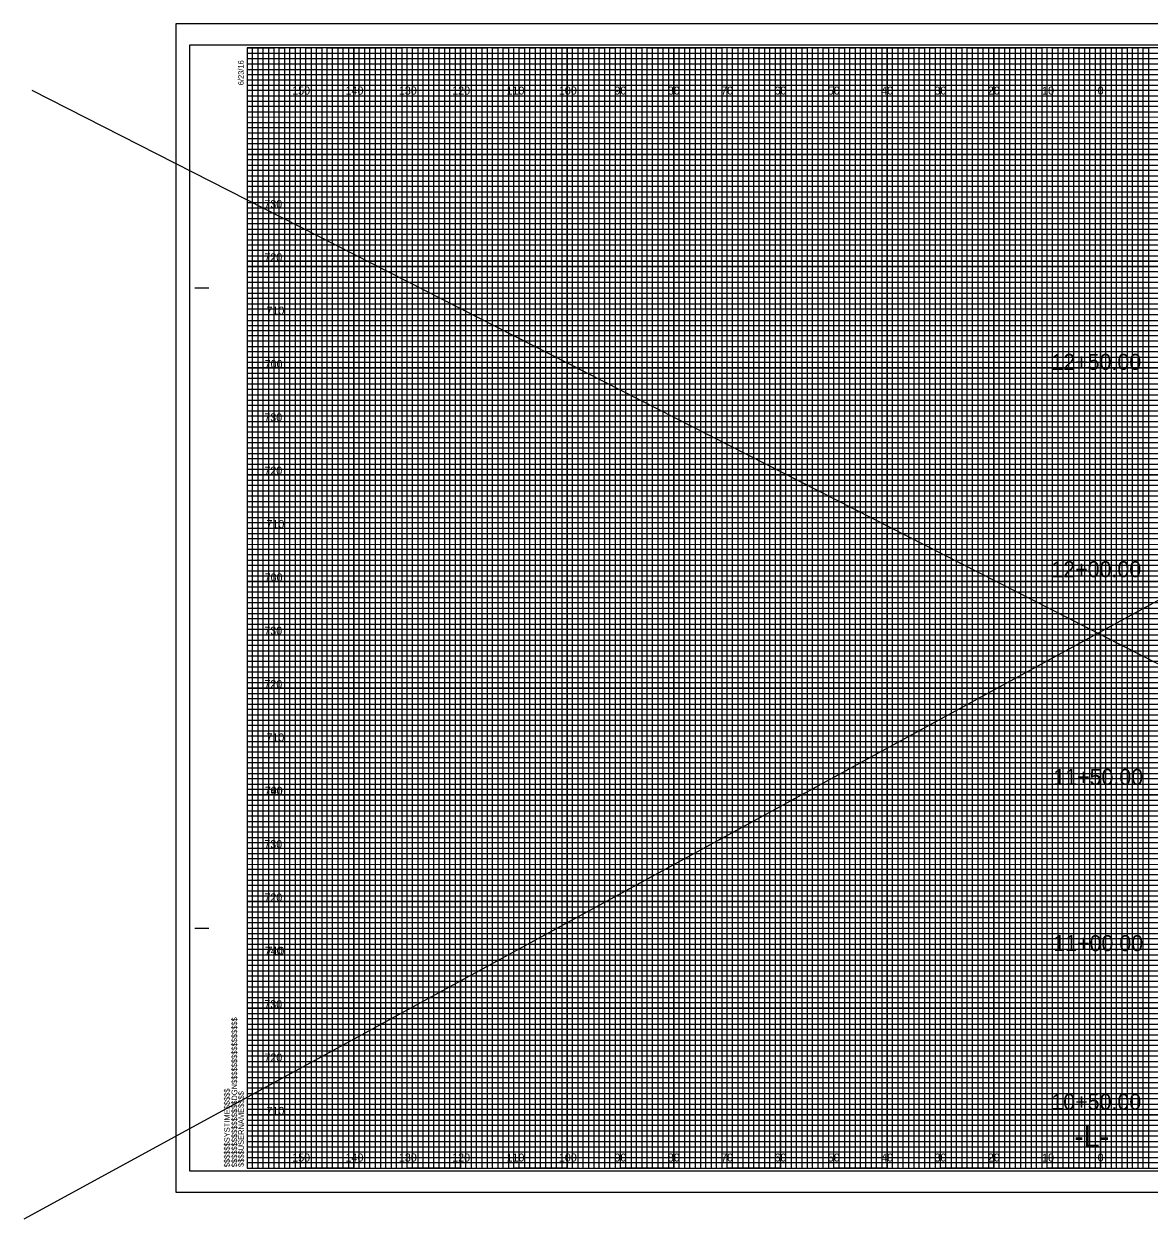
# Model space of a CAD drawing. Extents: x -98 to 717, y -10 to 1974.
# Drawn here: x -41.9 to 169.1, y -9.5 to 214.5 of the extents above; entities that cross this region are included whole.
import ezdxf

# ---------------------------------------------------------------- set-up
doc = ezdxf.new("R2010")
doc.units = 0
for name, color, linetype in [('Default', 7, 'Continuous'), ('Exist XS Center Line Elevation Label', 7, 'Continuous'), ('Prop CMT Conc Surface', 7, 'Continuous'), ('Prop CMT Concrete Structures', 7, 'Continuous'), ('Prop CMT Pvmt Course 1', 7, 'Continuous'), ('Prop CMT Pvmt Course 1 CG', 7, 'Continuous'), ('Prop CMT Pvmt Course 2', 7, 'Continuous'), ('Prop CMT Pvmt Course 3', 7, 'Continuous'), ('Prop CMT Pvmt Surface', 7, 'Continuous'), ('Prop CMT Shld Paved Course 3', 7, 'Continuous'), ('Prop CMT Subgrade Earthwork', 7, 'Continuous'), ('Prop XS Earthwork Shape', 7, 'Continuous'), ('Prop XS Elevation Labels', 7, 'Continuous'), ('Typical Curb CELL', 7, 'Continuous')]:
    doc.layers.add(name, color=color, linetype=linetype)

msp = doc.modelspace()

# ---------------------------------------------------------------- linework, layer by layer
at = {"layer": 'Default'}
for p, q in [((351.51, 205.03), (-41.86, -9.54)), ((-40.39, 202.07), (375.17, -9.54))]:
    msp.add_line(p, q, dxfattribs=at)
at = {"layer": 'Exist XS Center Line Elevation Label'}
for p, q in [((0, 209), (260, 209)), ((260, 207.98), (0, 207.98)), ((0, 207.98), (0, 207)), ((0, 207), (260, 207)), ((260, 205.89), (0, 205.89)), ((0, 205.89), (0, 204)), ((0, 204), (320, 204))]:
    msp.add_line(p, q, dxfattribs=at)
for points in [[(0, 203), (270, 203), (320, 203), (320, 202), (0, 202)], [(0, 201), (320, 201), (320, 199), (0, 199)], [(0, 198), (320, 198), (320, 197), (0, 196.98)], [(0, 196), (320, 196), (320, 194), (0, 194)], [(0, 193), (320, 193), (320, 192), (0, 192)], [(0, 191), (320, 191), (320, 189), (0, 189)], [(0, 188), (320, 188), (320, 187), (0, 187)], [(0, 186), (320, 186), (320, 184), (0, 184)], [(0, 183), (320, 183), (320, 182), (0, 182)], [(0, 181), (320, 181), (320, 179), (0, 179)], [(0, 178), (320, 178), (320, 177), (0, 177)], [(0, 176), (320, 176), (320, 173.95), (320, 173), (320, 172), (0, 172)], [(0, 174), (320, 174), (320, 173), (0, 173)], [(0, 171), (320, 171), (320, 169), (0, 169.03)], [(0, 169.03), (320, 169), (320, 168), (0, 168)], [(0, 167), (320, 167), (320, 166), (0, 166)], [(0, 164), (320, 164), (320, 163), (0, 163)], [(0, 162), (320, 162), (320, 161), (0, 161)], [(-0.07, 158.89), (320, 158.89), (320, 157.88), (-0.07, 157.88)], [(0, 157), (320, 157), (320, 156), (0, 156)], [(0, 154), (320, 154), (320, 153), (0, 153)], [(0, 152), (320, 152), (320, 151), (0, 151)], [(0, 149), (320, 149), (320, 148), (0, 148)], [(0, 147), (320, 147), (320, 146), (0, 146)], [(0, 144), (320, 144), (320, 143), (0, 143)], [(0, 142), (320, 142), (320, 141), (0, 141)], [(0, 139), (320, 139), (319.99, 137.98), (0, 138)], [(0, 137), (320, 137), (320, 136), (0, 136)], [(0, 134), (320, 134), (320, 133), (0, 133)], [(0, 132), (320, 132), (320, 131), (0, 131)], [(0, 129), (320, 129), (320, 128), (0, 128)], [(0, 127), (320, 127), (320, 126), (0, 126)], [(0, 124), (320, 124), (320, 123), (0, 123)], [(0, 122), (320, 122), (320, 121), (0, 121)], [(0, 119), (320, 119), (320, 118), (0, 118)], [(0, 116.99), (320.07, 116.91), (320, 116), (0, 116)], [(0, 114), (320, 114), (320, 113), (0, 113)], [(0, 112), (320, 112), (320, 111), (0, 111)], [(0, 109), (320, 109), (320, 108), (0, 108)], [(0, 107), (320, 107), (320, 106), (0, 106)], [(0, 104), (320, 104), (320, 103), (0, 103)], [(0, 102), (320, 102), (320, 101), (0, 101)], [(0, 99), (320, 99), (320, 98), (0, 98)], [(0, 97), (320, 97), (320, 96), (0, 96)], [(0, 94), (320, 94), (320, 93), (0, 93)], [(0, 92), (320, 92), (320, 91), (0, 91)], [(0, 89), (320, 89), (320, 88), (0, 88)], [(0, 87), (320, 87), (320, 86), (0, 86)], [(0, 84), (320, 84), (320, 83), (0, 83)], [(0, 82), (320, 82), (320, 81), (0, 81)], [(0, 79), (320, 79), (319.99, 77.98), (0, 78)], [(0, 77), (320, 77), (320, 76), (0, 76)], [(0, 74), (320, 74), (320, 73), (0, 73)], [(0, 72), (320, 72), (320, 71), (0, 71)], [(0, 69), (320, 69), (320, 68), (0, 68)], [(0, 67), (320, 67), (320, 66), (0, 66)], [(0, 64), (320, 64), (320, 63), (0, 63)], [(0, 62), (320, 62), (320, 61), (0, 61)], [(0, 59), (320, 59), (320, 58), (0, 58)], [(0, 56.99), (320.07, 56.91), (320, 56), (0, 56)], [(0, 54), (320, 54), (320, 53), (0, 53)], [(0, 52), (320, 52), (320, 51), (0, 51)], [(0, 49), (320, 49), (320, 48), (0, 48)], [(0, 47), (320, 47), (320, 46), (0, 46)], [(0, 44), (320, 44), (320, 43), (0, 43)], [(0, 42), (320, 42), (320, 41), (0, 41)], [(0, 39), (320, 39), (320, 38), (0, 38)], [(0, 37), (320, 37), (320, 36), (0, 36)], [(0, 34), (320, 34), (320, 33), (0, 33)], [(0, 32), (320, 32), (320, 31), (0, 31)], [(0, 29), (320, 29), (320, 28), (0, 28)], [(0, 27), (320, 27), (320, 26), (0, 26)], [(0, 24), (320, 24), (320, 23), (0, 23)], [(0, 22), (320, 22), (320, 21), (0, 21)], [(0, 19), (320, 19), (320, 18), (0, 18)], [(0, 17), (320, 17), (320, 16), (0, 16)], [(0, 14), (320, 14), (320, 13), (0, 13)], [(0, 12), (320, 12), (320, 11), (0, 11)], [(0, 9), (320, 9), (320, 8), (0, 8)], [(0, 7), (320, 7), (320, 6), (0, 6)], [(0, 4), (320, 4), (320, 3), (0, 3)], [(0, 2), (320, 2), (320, 1), (0, 1)]]:
    msp.add_lwpolyline(points, dxfattribs=at)
at = {"layer": 'Prop CMT Conc Surface'}
for p, q in [((-9.8, 165), (-7.3, 165)), ((-9.7, 165), (-7.2, 165)), ((-9.8, 45), (-7.3, 45)), ((-9.7, 45), (-7.2, 45)), ((0, 0), (0, 0)), ((0, 0), (0, 0)), ((0, 0), (0, 0)), ((0, 0), (0, 0)), ((0, 0), (0, 0)), ((0, 0), (0, 0)), ((0, 0), (0, 0))]:
    msp.add_line(p, q, dxfattribs=at)
msp.add_lwpolyline([(320, 210), (0, 210), (0, 0), (320, 0)], close=True, dxfattribs=at)
at = {"layer": 'Prop CMT Concrete Structures'}
for p, q in [((10, 0), (10, 210)), ((20, 0), (20, 210)), ((30, 0), (30, 210)), ((40, 0), (40, 210)), ((50, 0), (50, 210)), ((60, 0), (60, 210)), ((70, 0), (70, 210)), ((80, 0), (80, 210)), ((90, 0), (90, 210)), ((100, 0), (100, 210)), ((110, 0), (110, 210)), ((120, 0), (120, 210)), ((130, 0), (130, 210)), ((140, 0), (140, 210)), ((150, 0), (150, 210)), ((160, 0), (160, 210)), ((0, 200), (320, 200)), ((0, 190), (320, 190)), ((0, 180), (320, 180)), ((0, 170), (320, 170)), ((0, 160), (320, 160)), ((0, 150), (320, 150)), ((0, 140), (320, 140)), ((0, 130), (320, 130)), ((0, 120), (320, 120)), ((0, 110), (320, 110)), ((0, 100), (320, 100)), ((0, 90), (320, 90)), ((0, 80), (320, 80)), ((0, 70), (320, 70)), ((0, 60), (320, 60)), ((0, 50), (320, 50)), ((0, 40), (320, 40)), ((0, 30), (320, 30)), ((0, 20), (320, 20)), ((0, 10), (320, 10))]:
    msp.add_line(p, q, dxfattribs=at)
at = {"layer": 'Prop CMT Pvmt Course 2'}
msp.add_lwpolyline([(-13.4, -4.5), (323.3, -4.5), (323.3, 214.5), (-13.4, 214.5)], close=True, dxfattribs=at)
at = {"layer": 'Prop CMT Pvmt Course 3'}
msp.add_lwpolyline([(-10.8, -0.5), (322.4, -0.5), (322.4, 210.5), (-10.8, 210.5)], close=True, dxfattribs=at)
at = {"layer": 'Prop CMT Pvmt Surface'}
for p, q in [((323.3, 214.5), (-13.4, 214.5)), ((-13.4, 214.5), (-13.4, -4.5)), ((-13.4, -4.5), (323.3, -4.5))]:
    msp.add_line(p, q, dxfattribs=at)
at = {"layer": 'Prop CMT Subgrade Earthwork'}
for points in [[(0, 0), (1, 0), (1, 210), (2, 210), (2, 0)], [(2, 0), (3, 0), (3, 210), (4, 210), (4, 0)], [(5, 0), (6, 0), (6, 210), (7, 210), (7, 0)], [(7, 0), (8, 0), (8, 210), (9, 210), (9, 0)], [(10, 0), (11, 0), (11, 210), (12, 210), (12, 0)], [(12, 0), (13, 0), (13, 210), (14, 210), (14, 0)], [(15, 0), (16, 0), (16, 210), (17, 210), (17, 0)], [(17, 0), (18, 0), (18, 210), (19, 210), (19, 0)], [(20, 0), (21, 0), (21, 210), (22, 210), (22, 0)], [(22, 0), (23, 0), (23, 210), (24, 210), (24, 0)], [(25, 0), (26, 0), (26, 210), (27, 210), (27, 0)], [(27, 0), (28, 0), (28, 210), (29, 210), (29, 0)], [(30, 0), (31, 0), (31, 210), (32, 210), (32, 0)], [(32, 0), (33, 0), (33, 210), (34, 210), (34, 0)], [(35, 0), (36, 0), (36, 210), (37, 210), (37, 0)], [(37, 0), (38, 0), (38, 210), (39, 210), (39, 0)], [(40, 0), (41, 0), (41, 210), (42, 210), (42, 0)], [(42, 0), (43, 0), (43, 210), (44, 210), (44, 0)], [(45, 0), (46, 0), (46, 210), (47, 210), (47, 0)], [(47, 0), (48, 0), (48, 210), (49, 210), (49, 0)], [(50, 0), (51, 0), (51, 210), (52, 210), (52, 0)], [(52, 0), (53, 0), (53, 210), (54, 210), (54, 0)], [(55, 0), (56, 0), (56, 210), (57, 210), (57, 0)], [(57, 0), (58, 0), (58, 210), (59, 210), (59, 0)], [(60, 0), (61, 0), (61, 210), (62, 210), (62, 0)], [(62, 0), (63, 0), (63, 210), (64, 210), (64, 0)], [(65, 0), (66, 0), (66, 210), (67, 210), (67, 0)], [(67, 0), (68, 0), (68, 210), (69, 210), (69, 0)], [(70, 0), (71, 0), (71, 210), (72, 210), (72, 0)], [(72, 0), (73, 0), (73, 210), (74, 210), (74, 0)], [(75, 0), (76, 0), (76, 210), (77, 210), (77, 0)], [(77, 0), (78, 0), (78, 210), (79, 210), (79, 0)], [(80, 0), (81, 0), (81, 210), (82, 210), (82, 0)], [(82, 0), (83, 0), (83, 210), (84, 210), (84, 0)], [(85, 0), (86, 0), (86, 210), (87, 210), (87, 0)], [(87, 0), (88, 0), (88, 210), (89, 210), (89, 0)], [(90, 0), (91, 0), (91, 210), (92, 210), (92, 0)], [(92, 0), (93, 0), (93, 210), (94, 210), (94, 0)], [(95, 0), (96, 0), (96, 210), (97, 210), (97, 0)], [(97, 0), (98, 0), (98, 210), (99, 210), (99, 0)], [(100, 0), (101, 0), (101, 210), (102, 210), (102, 0)], [(102, 0), (103, 0), (103, 210), (104, 210), (104, 0)], [(105, 0), (106, 0), (106, 210), (107, 210), (107, 0)], [(107, 0), (108, 0), (108, 210), (109, 210), (109, 0)], [(110, 0), (111, 0), (111, 210), (112, 210), (112, 0)], [(112, 0), (113, 0), (113, 210), (114, 210), (114, 0)], [(115, 0), (116, 0), (116, 210), (117, 210), (117, 0)], [(117, 0), (118, 0), (118, 210), (119, 210), (119, 0)], [(120, 0), (121, 0), (121, 210), (122, 210), (122, 0)], [(122, 0), (123, 0), (123, 210), (124, 210), (124, 0)], [(125, 0), (126, 0), (126, 210), (127, 210), (127, 0)], [(127, 0), (128, 0), (128, 210), (129, 210), (129, 0)], [(130, 0), (131, 0), (131, 210), (132, 210), (132, 0)], [(132, 0), (133, 0), (133, 210), (134, 210), (134, 0)], [(135, 0), (136, 0), (136, 210), (137, 210), (137, 0)], [(137, 0), (138, 0), (138, 210), (139, 210), (139, 0)], [(140, 0), (141, 0), (141, 210), (142, 210), (142, 0)], [(142, 0), (143, 0), (143, 210), (144, 210), (144, 0)], [(145, 0), (146, 0), (146, 210), (147, 210), (147, 0)], [(147, 0), (148, 0), (148, 210), (149, 210), (149, 0)], [(150, 0), (151, 0), (151, 210), (152, 210), (152, 0)], [(152, 0), (153, 0), (153, 210), (154, 210), (154, 0)], [(155, 0), (156, 0), (156, 210), (157, 210), (157, 0)], [(157, 0), (158, 0), (158, 210), (159, 210), (159, 0)], [(160, 0), (161, 0), (161, 210), (162, 210), (162, 0)], [(162, 0), (163, 0), (163, 210), (164, 210), (164, 0)], [(165, 0), (166, 0), (166, 210), (167, 210), (167, 0)], [(167, 0), (168, 0), (168, 210), (169, 210), (169, 0)]]:
    msp.add_lwpolyline(points, dxfattribs=at)
at = {"layer": 'Prop XS Elevation Labels'}
for p, q in [((10, 210), (0, 210)), ((10, 0), (10, 210)), ((30, 210), (20, 210)), ((20, 210), (20, 0)), ((30, 0), (30, 210)), ((50, 210), (40, 210)), ((40, 210), (40, 0)), ((50, 0), (50, 210)), ((70, 210), (60, 210)), ((60, 210), (60, 0)), ((70, 0), (70, 210)), ((90, 210), (80, 210)), ((80, 210), (80, 0)), ((90, 0), (90, 210)), ((110, 210), (100, 210)), ((100, 210), (100, 0)), ((110, 0), (110, 210)), ((130, 210), (120, 210)), ((120, 210), (120, 0)), ((130, 0), (130, 210)), ((150, 210), (140, 210)), ((140, 210), (140, 0)), ((150, 0), (150, 210)), ((170, 210), (160, 210)), ((160, 210), (160, 0)), ((20, 0), (10, 0)), ((40, 0), (30, 0)), ((60, 0), (50, 0)), ((80, 0), (70, 0)), ((100, 0), (90, 0)), ((120, 0), (110, 0)), ((140, 0), (130, 0)), ((160, 0), (150, 0))]:
    msp.add_line(p, q, dxfattribs=at)
for points in [[(0, 200), (320, 200), (320, 190), (0, 190)], [(0, 180), (320, 180), (320, 170), (0, 170)], [(0, 160), (320, 160), (320, 150), (0, 150)], [(0, 140), (320, 140), (320, 130), (0, 130)], [(0, 120), (320, 120), (320, 110), (0, 110)], [(0, 100), (320, 100), (320, 90), (0, 90)], [(0, 80), (320, 80), (320, 70), (0, 70)], [(0, 60), (320, 60), (320, 50), (0, 50)], [(0, 40), (320, 40), (320, 30), (0, 30)], [(0, 20), (320, 20), (320, 10), (0, 10)]]:
    msp.add_lwpolyline(points, dxfattribs=at)
at = {"layer": 'Typical Curb CELL'}
for points in [[(0, 210), (5, 210), (5, 0), (15, 0), (15, 210), (25, 210), (25, 0), (35, 0), (35, 210), (45, 210), (45, 0), (55, 0), (55, 210), (65, 210), (65, 0), (75, 0), (75, 210), (85, 210), (85, 0), (95, 0), (95, 210), (105, 210), (105, 0), (115, 0), (115, 210), (125, 210), (125, 0), (135, 0), (135, 210), (145, 210), (145, 0), (155, 0), (155, 210), (165, 210), (165, 0), (175, 0)], [(0, 205), (275, 205)], [(0, 185), (320, 185), (320, 195), (0, 195)], [(0, 165), (320, 165), (320, 175), (0, 175)], [(0, 145), (320, 145), (320, 155), (0, 155)], [(0, 125), (320, 125), (320, 135), (0, 135)], [(0, 105), (320, 105), (320, 115), (0, 115)], [(0, 85), (320, 85), (320, 95), (0, 95)], [(0, 65), (320, 65), (320, 75), (0, 75)], [(0, 45), (320, 45), (320, 55), (0, 55)], [(0, 25), (320, 25), (320, 35), (0, 35)], [(0, 5), (320, 5), (320, 15), (0, 15)]]:
    msp.add_lwpolyline(points, dxfattribs=at)

# ---------------------------------------------------------------- texts
at = {"layer": 'Prop CMT Conc Surface'}
for s, p in [('6/23/16', (-0.65, 203)), ('$$$$$$$$$$$$$$$$DGN$$$$$$$$$$$$$$$$', (-1.88, 0.18)), ('$$$$$$SYSTIME$$$$$', (-3.26, 0.18)), ('$$$$USERNAME$$$$', (-0.62, 0.23))]:
    msp.add_text(s, height=1.05, rotation=90, dxfattribs=at).set_placement(p)
at = {"layer": 'Prop CMT Pvmt Course 1'}
for s, p in [('12+50.00', (150.77, 149.65)), ('12+00.00', (150.77, 110.78)), ('11+50.00', (151.13, 71.84)), ('11+00.00', (151.13, 40.69)), ('10+50.00', (150.77, 10.96))]:
    msp.add_text(s, height=3, dxfattribs=at).set_placement(p)
at = {"layer": 'Prop CMT Pvmt Course 1 CG'}
for s, p in [('730', (3.22, 180)), ('720', (3.23, 170)), ('710', (3.61, 160)), ('700', (3.28, 150)), ('730', (3.22, 140)), ('720', (3.23, 130)), ('710', (3.61, 120)), ('700', (3.28, 110)), ('730', (3.22, 100)), ('720', (3.23, 90)), ('710', (3.61, 80)), ('700', (3.28, 70)), ('740', (3.3, 70)), ('730', (3.22, 60)), ('720', (3.23, 50)), ('740', (3.3, 40)), ('710', (3.61, 40)), ('730', (3.22, 30)), ('720', (3.23, 20)), ('710', (3.61, 10))]:
    msp.add_text(s, height=1.5, dxfattribs=at).set_placement(p)
at = {"layer": 'Prop CMT Shld Paved Course 3'}
msp.add_text('-L-', height=4, dxfattribs=at).set_placement((155.06, 4))
at = {"layer": 'Prop XS Earthwork Shape'}
for s, p in [('150', (8.44, 201.25)), ('140', (18.44, 201.25)), ('130', (28.44, 201.25)), ('120', (38.44, 201.25)), ('110', (48.62, 201.25)), ('100', (58.44, 201.25)), ('90', (68.86, 201.25)), ('80', (78.86, 201.25)), ('70', (88.86, 201.25)), ('60', (98.86, 201.25)), ('50', (108.86, 201.25)), ('40', (118.86, 201.25)), ('30', (128.86, 201.25)), ('20', (138.86, 201.25)), ('10', (149.04, 201.25)), ('0', (159.45, 201.25)), ('0', (159.45, 201.25)), ('150', (8.44, 1.25)), ('140', (18.44, 1.25)), ('130', (28.44, 1.25)), ('120', (38.44, 1.25)), ('110', (48.62, 1.25)), ('100', (58.44, 1.25)), ('90', (68.86, 1.25)), ('80', (78.86, 1.25)), ('70', (88.86, 1.25)), ('60', (98.86, 1.25)), ('50', (108.86, 1.25)), ('40', (118.86, 1.25)), ('30', (128.86, 1.25)), ('20', (138.86, 1.25)), ('10', (149.04, 1.25)), ('0', (159.45, 1.25)), ('0', (159.45, 1.25))]:
    msp.add_text(s, height=1.5, dxfattribs=at).set_placement(p)

doc.saveas('drawing.dxf')
